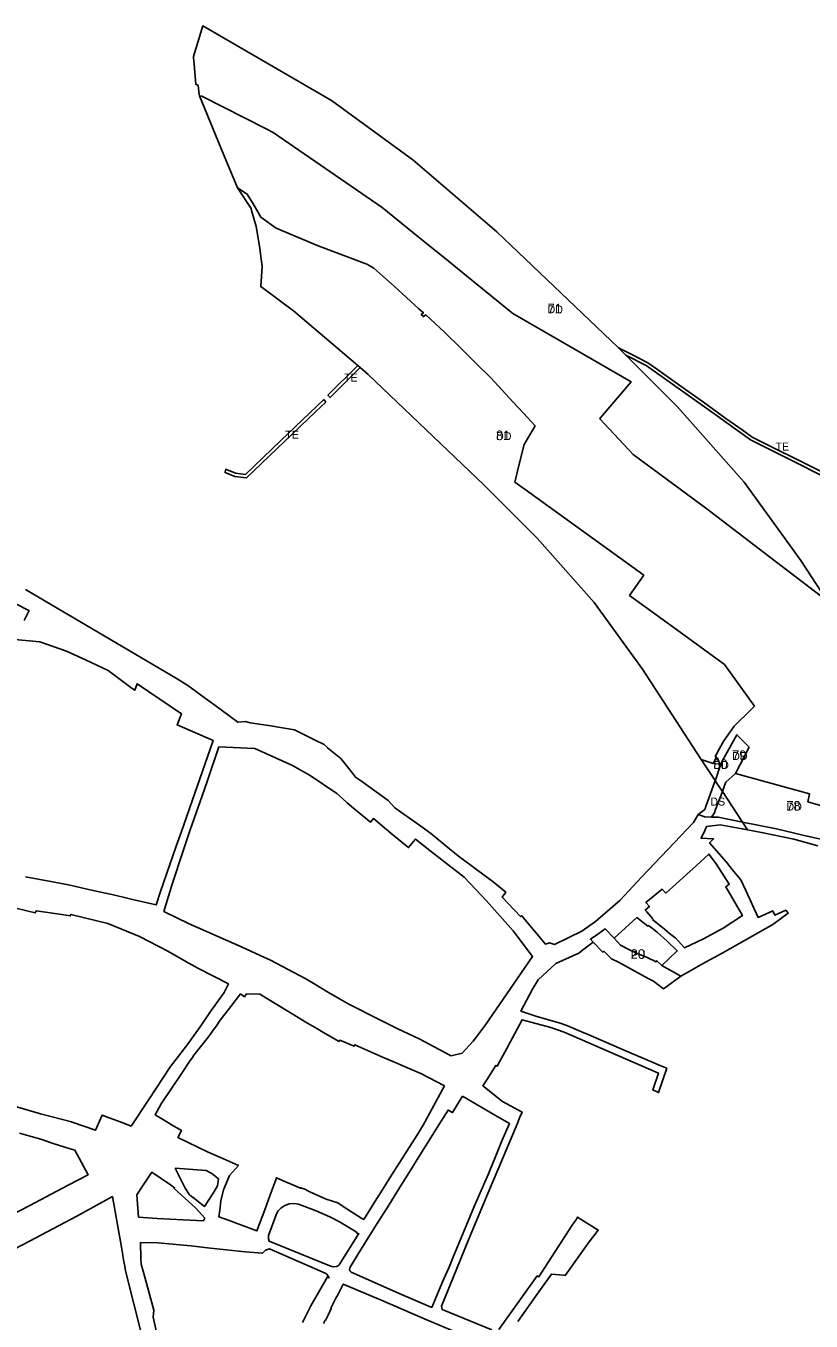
# Model space of a CAD drawing. Extents: x -545758 to -541641, y -1153152 to -1149975.
# Drawn here: x -544135 to -543644, y -1151498 to -1150689 of the extents above; entities that cross this region are included whole.
import ezdxf

# ---------------------------------------------------------------- set-up
doc = ezdxf.new("R2010")
doc.units = 0
for name, color, linetype in [('90320013', 7, 'Continuous'), ('90330013', 7, 'Continuous'), ('90330023', 7, 'Continuous'), ('90400013', 7, 'Continuous'), ('90450013', 7, 'Continuous'), ('90450023', 7, 'Continuous'), ('ID_navrh', 7, 'Continuous')]:
    doc.layers.add(name, color=color, linetype=linetype)

msp = doc.modelspace()

# ---------------------------------------------------------------- linework, layer by layer
at = {"layer": '90320013'}
msp.add_lwpolyline([(-543709.68, -1151176.38), (-543704.49, -1151161.98), (-543704.069, -1151160.82), (-543702.795, -1151162.777), (-543699.584, -1151167.645), (-543703.84, -1151178.88), (-543704.58, -1151180.83), (-543706.27, -1151183.57), (-543710.63, -1151183.4), (-543714.64, -1151182), (-543710.55, -1151178.78)], close=True, dxfattribs=at)
at = {"layer": '90330013'}
msp.add_lwpolyline([(-543622.39, -1151180.97), (-543646.12, -1151174.04), (-543645.1, -1151169.14), (-543691.46, -1151156.42), (-543682.89, -1151139.83), (-543690.45, -1151132.16), (-543699.75, -1151148.74), (-543701.13, -1151152.25), (-543700.92, -1151151.1), (-543702.64, -1151146.72), (-543703.3, -1151146.24), (-543704.04, -1151145.69), (-543703.28, -1151144.33), (-543701.31, -1151140.82), (-543698.59, -1151135.95), (-543692.28, -1151126.74), (-543681.39, -1151116.11), (-543679.42, -1151114.2), (-543698.26, -1151088.2), (-543728.18, -1151066.45), (-543757.51, -1151045.12), (-543748.74, -1151032.49), (-543822.74, -1150978.92), (-543829.21, -1150974.23), (-543826.66, -1150963.9), (-543823.42, -1150950.72), (-543816.58, -1150939.09), (-543823.76, -1150931.28), (-543830.39, -1150924.08), (-543837.13, -1150916.75), (-543844.45, -1150908.84), (-543853.71, -1150899.71), (-543862.68, -1150890.87), (-543873.19, -1150880.51), (-543884.94, -1150869.81), (-543886.25, -1150870.84), (-543887.76, -1150869.57), (-543886.4, -1150868.47), (-543889.18, -1150865.96), (-543904.7, -1150851.96), (-543911.64, -1150845.71), (-543917.39, -1150840.52), (-543921.63, -1150838.04), (-543952.16, -1150826.63), (-543978.35, -1150815.7), (-543987.95, -1150808.86), (-543990.71, -1150803.91), (-543992.64, -1150800.45), (-543996.47, -1150794.31), (-544002.61, -1150790.35), (-544005.66, -1150782.96), (-544012.92, -1150765.35), (-544026.25, -1150733.04), (-544024.7, -1150733.15), (-543984.63, -1150753.63), (-543980.18, -1150755.91), (-543912.05, -1150802.81), (-543889.76, -1150820.87), (-543886.65, -1150823.39), (-543870.95, -1150836.1), (-543865.01, -1150840.92), (-543831.46, -1150868.11), (-543830.4, -1150868.97), (-543756.47, -1150911.73), (-543776, -1150934.43), (-543776.22, -1150934.68), (-543755.27, -1150957.07), (-543709.38, -1150990.96), (-543670.14, -1151020.9), (-543608.97, -1151067.59)], dxfattribs=at)
at = {"layer": '90330023'}
for points in [[(-543831.46, -1150868.11), (-543831.46, -1150868.11), (-543865.01, -1150840.92), (-543870.95, -1150836.1), (-543886.65, -1150823.39), (-543889.76, -1150820.87), (-543912.05, -1150802.81), (-543980.18, -1150755.91), (-543984.63, -1150753.63), (-544024.7, -1150733.15), (-544026.25, -1150733.04), (-544026.37, -1150732.2), (-544027.19, -1150726.47), (-544028.18, -1150725.94), (-544028.6, -1150725.71), (-544029.66, -1150713.36), (-544030.04, -1150708.97), (-544030.08, -1150708.47), (-544024.212, -1150689.258), (-543943.707, -1150735.843), (-543892.905, -1150773.039), (-543840.462, -1150817.893), (-543764.769, -1150890.108), (-543727.838, -1150927.049), (-543685.997, -1150974.326), (-543650.498, -1151023.182), (-543634.042, -1151048.453), (-543670.14, -1151020.9), (-543709.38, -1150990.96), (-543755.27, -1150957.07), (-543776.22, -1150934.68), (-543776, -1150934.43), (-543756.47, -1150911.73), (-543830.4, -1150868.97)], [(-543779.683, -1151049.534), (-543815.282, -1151009.31), (-543848.631, -1150975.952), (-543920.938, -1150906.967), (-543925.852, -1150902.765), (-543927.383, -1150901.455), (-543967.455, -1150867.181), (-543988.016, -1150852.128), (-543987.15, -1150839.52), (-543988.46, -1150828.29), (-543990.46, -1150816.88), (-543990.87, -1150814.52), (-543993.76, -1150804.51), (-543994.07, -1150803.43), (-544002.61, -1150790.35), (-543996.47, -1150794.31), (-543992.64, -1150800.45), (-543990.71, -1150803.91), (-543987.95, -1150808.86), (-543978.35, -1150815.7), (-543952.16, -1150826.63), (-543921.63, -1150838.04), (-543917.39, -1150840.52), (-543911.64, -1150845.71), (-543904.7, -1150851.96), (-543889.18, -1150865.96), (-543886.4, -1150868.47), (-543887.76, -1150869.57), (-543886.25, -1150870.84), (-543884.94, -1150869.81), (-543873.19, -1150880.51), (-543862.68, -1150890.87), (-543853.71, -1150899.71), (-543844.45, -1150908.84), (-543837.13, -1150916.75), (-543830.39, -1150924.08), (-543823.76, -1150931.28), (-543816.58, -1150939.09), (-543823.42, -1150950.72), (-543826.66, -1150963.9), (-543829.21, -1150974.23), (-543822.74, -1150978.92), (-543748.74, -1151032.49), (-543757.51, -1151045.12), (-543728.18, -1151066.45), (-543698.26, -1151088.2), (-543679.42, -1151114.2), (-543681.39, -1151116.11), (-543692.28, -1151126.74), (-543698.59, -1151135.95), (-543701.31, -1151140.82), (-543703.28, -1151144.33), (-543704.04, -1151145.69), (-543703.3, -1151146.24), (-543705.29, -1151150.15), (-543712.747, -1151147.495), (-543749.382, -1151091.238)], [(-543703.5, -1151159.25), (-543701.13, -1151152.25), (-543699.75, -1151148.74), (-543690.45, -1151132.16), (-543682.89, -1151139.83), (-543691.46, -1151156.42), (-543697.39, -1151161.85), (-543698.15, -1151163.86), (-543699.584, -1151167.645), (-543702.795, -1151162.777), (-543704.069, -1151160.82)], [(-543704.069, -1151160.82), (-543712.747, -1151147.495), (-543705.29, -1151150.15), (-543703.3, -1151146.24), (-543702.64, -1151146.72), (-543700.92, -1151151.1), (-543701.13, -1151152.25), (-543703.5, -1151159.25)], [(-543665.68, -1151191), (-543686.982, -1151186.756), (-543699.584, -1151167.645), (-543698.15, -1151163.86), (-543697.39, -1151161.85), (-543691.46, -1151156.42), (-543645.1, -1151169.14), (-543646.12, -1151174.04), (-543622.39, -1151180.97), (-543621.56, -1151181.15), (-543619.19, -1151184.73), (-543612.4, -1151194.99), (-543608.87, -1151200.33), (-543609.43, -1151200.65), (-543619.29, -1151202.61), (-543637.18, -1151197.56), (-543649.23, -1151194.95)]]:
    msp.add_lwpolyline(points, close=True, dxfattribs=at)
msp.add_lwpolyline([(-543639.96, -1151201.49), (-543654.84, -1151197.32), (-543654.879, -1151197.312), (-543675.179, -1151193.284), (-543683.806, -1151191.571), (-543686.982, -1151186.756), (-543665.68, -1151191), (-543649.23, -1151194.95), (-543637.18, -1151197.56)], dxfattribs=at)
at = {"layer": '90400013'}
msp.add_lwpolyline([(-543610.53, -1150983.63), (-543681.92, -1150947.91), (-543696.76, -1150937.34), (-543702.88, -1150932.98), (-543702.88, -1150932.98), (-543747.19, -1150901.41), (-543759.981, -1150894.897), (-543764.552, -1150890.325), (-543756.2, -1150894.58), (-543746.15, -1150899.7), (-543740.79, -1150903.51), (-543726.08, -1150914), (-543711.46, -1150924.42), (-543697.36, -1150934.46), (-543687.16, -1150941.72), (-543680.89, -1150946.19), (-543678.05, -1150947.61), (-543665.64, -1150953.82), (-543653.68, -1150959.8), (-543637.45, -1150967.92)], dxfattribs=at)
for points in [[(-543925.852, -1150902.765), (-543944.64, -1150921.44), (-543946.01, -1150919.98), (-543927.383, -1150901.455)], [(-543947.35, -1150924.29), (-543953.47, -1150930.15), (-543977.89, -1150953.5), (-543996.79, -1150971.58), (-544004.18, -1150970.7), (-544010.23, -1150968.29), (-544010.26, -1150967.9), (-544009.85, -1150966.29), (-544009.35, -1150966.49), (-544003.69, -1150968.75), (-543997.5, -1150969.49), (-543975.44, -1150948.39), (-543948.6, -1150922.72)]]:
    msp.add_lwpolyline(points, close=True, dxfattribs=at)
at = {"layer": '90450013'}
for points in [[(-544135.83, -1151060.82), (-544132.77, -1151054.51), (-544133.31, -1151054.25), (-544155.85, -1151042.75)], [(-544135.01, -1151041.31), (-544040.31, -1151097.11), (-544037.9, -1151098.61), (-544034.19, -1151100.86), (-544032.91, -1151101.71), (-544023.35, -1151108.8), (-544016.68, -1151113.74), (-544002.35, -1151124.26), (-543997.51, -1151123.83), (-543994.53, -1151124.74), (-543981.61, -1151126.57), (-543975.61, -1151127.67), (-543966.97, -1151129.16), (-543953.58, -1151135.75), (-543948.46, -1151138.26), (-543946.15, -1151140.23), (-543946.19, -1151140.41), (-543937.89, -1151147.01), (-543931.37, -1151155.21), (-543928.69, -1151158.64), (-543925.06, -1151161.21), (-543920.47, -1151164.49), (-543908.28, -1151173.21), (-543904.16, -1151177.72), (-543888.04, -1151189.17), (-543881.98, -1151193.72), (-543868.86, -1151204.5), (-543863.57, -1151208.55), (-543856.58, -1151213.86), (-543853.29, -1151216.4), (-543842.74, -1151224.1), (-543834.93, -1151230.45), (-543837.14, -1151233.56), (-543825.8, -1151245.7), (-543825.07, -1151245.07), (-543810.15, -1151262.93), (-543807.5, -1151262.19), (-543804.52, -1151263.25), (-543787.44, -1151254.86), (-543778.92, -1151248.83), (-543763.74, -1151235.65), (-543749.81, -1151220.95), (-543717.6, -1151186.99), (-543714.64, -1151182), (-543710.63, -1151183.4), (-543706.27, -1151183.57), (-543702.17, -1151183.73), (-543686.982, -1151186.756), (-543683.806, -1151191.571), (-543687.14, -1151190.91), (-543700.87, -1151188.52), (-543709.48, -1151189.44), (-543710.44, -1151192.02), (-543712.86, -1151196.79), (-543705.09, -1151197.25), (-543707.45, -1151199.51), (-543707.61, -1151199.67), (-543696.99, -1151211.72), (-543693.35, -1151216.4), (-543690.31, -1151219.98), (-543687.97, -1151222.83), (-543684.97, -1151229.45), (-543680.64, -1151238.98), (-543677.28, -1151246.3), (-543668.09, -1151242.1), (-543666.73, -1151244.88), (-543660.02, -1151241.79), (-543658.4, -1151243.65), (-543667.96, -1151250.69), (-543683.79, -1151259.72), (-543699.65, -1151268.52), (-543712.31, -1151275.52), (-543718.88, -1151279.16), (-543725.48, -1151282.91), (-543737.45, -1151276.39), (-543727.73, -1151267.21), (-543734.01, -1151261.04), (-543740.02, -1151255.78), (-543743.2, -1151253.18), (-543745.79, -1151251.32), (-543746.06, -1151251.68), (-543752.98, -1151246.32), (-543767.08, -1151259.24), (-543772.73, -1151253.4), (-543777.43, -1151256.71), (-543782.02, -1151259.94), (-543780.39, -1151261.65), (-543786.91, -1151266.72), (-543789.27, -1151268.6), (-543803.59, -1151275.15), (-543814.61, -1151285.21), (-543818.17, -1151291.08), (-543825.45, -1151304.75), (-543816.12, -1151307.9), (-543801, -1151312.35), (-543796.67, -1151313.74), (-543785.02, -1151318.75), (-543784.788, -1151318.85), (-543763.824, -1151327.87), (-543738.03, -1151338.97), (-543734.37, -1151340.55), (-543739.44, -1151355.73), (-543743.07, -1151354.05), (-543739.57, -1151343.55), (-543764.831, -1151332.615), (-543798.52, -1151318.03), (-543806.71, -1151314.94), (-543824.69, -1151310.23), (-543832.19, -1151324.27), (-543834.23, -1151328.1), (-543838.72, -1151336.43), (-543840.3, -1151339.22), (-543841.06, -1151338.74), (-543846.72, -1151347.68), (-543849.15, -1151351.46), (-543836.99, -1151361.24), (-543824.677, -1151367.856), (-543826.23, -1151371.557), (-543827.44, -1151374.44), (-543839.67, -1151403.58), (-543846.73, -1151420.31), (-543858.23, -1151447.61), (-543875.12, -1151489.24), (-543874.59, -1151491.33), (-543843.54, -1151503.88)], [(-544135.07, -1151220.92), (-544119.1, -1151223.83), (-544108.2, -1151225.81), (-544093.63, -1151229.29), (-544079.19, -1151232.44), (-544072.2, -1151234), (-544068.15, -1151235), (-544061.61, -1151236.53), (-544053.24, -1151238.41), (-544050.68, -1151230.02), (-544040.78, -1151201.75), (-544037.55, -1151192.52), (-544017.79, -1151135.66), (-544040.27, -1151126.03), (-544037.55, -1151118.98), (-544051.12, -1151109.86), (-544065.3, -1151100.32), (-544066.7, -1151104.36), (-544068.3, -1151103.16), (-544083.41, -1151091.9), (-544097.44, -1151085.42), (-544109.42, -1151079.88), (-544125.96, -1151074.03), (-544141.57, -1151072.66)], [(-544143.24, -1151363.76), (-544125.62, -1151369.07), (-544106.19, -1151374.05), (-544105.76, -1151374.17), (-544091.17, -1151379.24), (-544087.07, -1151369.74), (-544084.39, -1151370.83), (-544073.5, -1151374.74), (-544069.05, -1151376.63), (-544057.84, -1151359.95), (-544044.72, -1151339.94), (-544044.28, -1151339.37), (-544034.31, -1151326.51), (-544025.92, -1151314.56), (-544019.28, -1151305.09), (-544010.85, -1151293.16), (-544008.14, -1151287.81), (-544027.27, -1151278.07), (-544034.7, -1151273.74), (-544046.02, -1151267.3), (-544063.84, -1151258.25), (-544083.61, -1151250.16), (-544106.61, -1151244.41), (-544107.01, -1151245.34), (-544112.23, -1151244.54), (-544128.27, -1151242.08), (-544128.88, -1151243.44), (-544147.79, -1151238.88)], [(-544144.7, -1151432.67), (-544132.32, -1151426.21), (-544118.9, -1151419.16), (-544108.27, -1151413.61), (-544096.71, -1151407.57), (-544095.8, -1151407.09), (-544104.06, -1151391.7), (-544107.12, -1151390.8), (-544117.64, -1151387.42), (-544125.4, -1151384.89), (-544131.37, -1151383.21), (-544138.76, -1151381.03)], [(-544062.12, -1151508.24), (-544072.41, -1151466.98), (-544072.89, -1151464.18), (-544073.73, -1151460.18), (-544074.39, -1151456.12), (-544075.02, -1151452.28), (-544080.63, -1151420.73), (-544102.81, -1151432.82), (-544117.9, -1151440.85), (-544132.09, -1151448.33), (-544146.42, -1151455.75)], [(-543839.26, -1151503.64), (-543833.07, -1151494.98), (-543815.25, -1151470.28), (-543814.22, -1151470.73), (-543812.44, -1151467.86), (-543793.35, -1151438.63), (-543790.79, -1151434.69), (-543790.01, -1151433.49), (-543777.13, -1151441.62), (-543782.81, -1151448.85), (-543797.73, -1151469.97), (-543798.82, -1151469.86), (-543806.39, -1151469.1), (-543812.24, -1151477.34), (-543816.4, -1151483.15), (-543827.34, -1151498.65)], [(-543961.96, -1151499.28), (-543956.79, -1151488.97), (-543946.34, -1151470.89), (-543945.23, -1151471.42), (-543946.8, -1151469.22), (-543947.72, -1151468.6), (-543982.6, -1151453.35), (-543984.94, -1151454.08), (-543986.86, -1151456.12), (-543997.75, -1151455.17), (-544009.64, -1151453.87), (-544021.2, -1151452.61), (-544031.57, -1151451.4), (-544047.8, -1151449.94), (-544052.19, -1151449.68), (-544063.02, -1151449.37), (-544062.99, -1151459.16), (-544062.69, -1151462.83), (-544061.48, -1151467.29), (-544061.07, -1151468.84), (-544054.77, -1151491.65), (-544055.23, -1151495.99), (-544051.57, -1151511.96)], [(-543865.54, -1151505.52), (-543885.28, -1151497.22), (-543913.17, -1151485.27), (-543915.75, -1151484.17), (-543936.43, -1151475.31), (-543938.15, -1151478.77), (-543940.18, -1151482.9), (-543940.36, -1151482.81), (-543942.23, -1151486.67), (-543944.1, -1151490.46), (-543943.93, -1151490.56), (-543945.93, -1151494.68), (-543947.56, -1151498.02), (-543947.76, -1151497.92), (-543948.81, -1151500.05)]]:
    msp.add_lwpolyline(points, dxfattribs=at)
for points in [[(-544043.35, -1151225.44), (-544048.52, -1151242.5), (-544032.78, -1151250.26), (-544009.98, -1151260.21), (-543999.56, -1151264.82), (-543988.26, -1151270.13), (-543981.96, -1151273), (-543959.76, -1151284.71), (-543958.85, -1151285.29), (-543954.29, -1151288.01), (-543945.7, -1151293.07), (-543938.88, -1151297.05), (-543932.89, -1151300.45), (-543914.35, -1151309.77), (-543902.35, -1151315.81), (-543888.99, -1151322.05), (-543869.81, -1151332.37), (-543869.08, -1151332.76), (-543862.17, -1151331.05), (-543855.28, -1151323.64), (-543853.15, -1151320.78), (-543847.66, -1151313.33), (-543843.07, -1151306.73), (-543832.4, -1151291.37), (-543829.61, -1151287.29), (-543818.28, -1151270.77), (-543827.85, -1151257.94), (-543830.34, -1151254.61), (-543846.98, -1151235.85), (-543853.8, -1151228.63), (-543860.89, -1151221.2), (-543876.76, -1151208.8), (-543881.27, -1151205.28), (-543891.32, -1151197.35), (-543891.6, -1151197.62), (-543895.65, -1151202.65), (-543897.46, -1151201.16), (-543906.64, -1151193.58), (-543917.59, -1151184.53), (-543919.49, -1151186.82), (-543929.88, -1151178.16), (-543933.97, -1151174.75), (-543937, -1151172.03), (-543940.51, -1151168.78), (-543957.16, -1151157.63), (-543968.25, -1151151.28), (-543991.7, -1151140.78), (-544014.15, -1151139.71), (-544021.35, -1151160.74), (-544024.64, -1151170.33), (-544032.04, -1151191.56), (-544036.38, -1151204.66)], [(-543743.22, -1151247.62), (-543735.7, -1151253.66), (-543732.87, -1151256.11), (-543729.14, -1151259.03), (-543729.01, -1151258.86), (-543723.13, -1151265.27), (-543711.35, -1151259.67), (-543699.04, -1151252.91), (-543687.02, -1151245.12), (-543697.47, -1151227.07), (-543695.27, -1151225.57), (-543703.52, -1151212.82), (-543704.8, -1151211.08), (-543707.93, -1151206.67), (-543715.75, -1151213.76), (-543722.05, -1151219.55), (-543734.92, -1151231.03), (-543737.26, -1151228.51), (-543747.36, -1151236.88), (-543745.16, -1151239.53), (-543747.71, -1151241.69), (-543746.82, -1151242.67), (-543743.07, -1151247.07)], [(-543912.31, -1151333.42), (-543929.15, -1151325.78), (-543929.62, -1151326.64), (-543938.63, -1151322.99), (-543939.02, -1151323.8), (-543939.51, -1151323.53), (-543950.3, -1151317.23), (-543952.87, -1151315.73), (-543960.21, -1151311.44), (-543967.39, -1151307.03), (-543988.58, -1151294.17), (-543996.82, -1151294.06), (-543998.16, -1151295.82), (-544000.55, -1151294.01), (-544006.68, -1151301.94), (-544013.25, -1151310.54), (-544015.73, -1151313.95), (-544017.7, -1151316.73), (-544019.62, -1151319.47), (-544021.43, -1151321.93), (-544029.71, -1151332.33), (-544030.71, -1151333.78), (-544032.11, -1151335.76), (-544037.32, -1151343.5), (-544050.12, -1151362.83), (-544053.99, -1151369.58), (-544050.83, -1151371.43), (-544044.58, -1151375.21), (-544043.68, -1151375.75), (-544038.57, -1151378.83), (-544037.56, -1151379.31), (-544039.79, -1151383.71), (-544020.87, -1151392.94), (-544013.11, -1151396.34), (-544001.97, -1151401.33), (-544007.43, -1151407.53), (-544011.35, -1151416.47), (-544012.87, -1151423.32), (-544013.54, -1151429.19), (-544014.17, -1151433.33), (-544007.69, -1151435.61), (-543990.4, -1151442.09), (-543985.44, -1151428.89), (-543982.37, -1151420.14), (-543978.64, -1151410.19), (-543978.21, -1151408.89), (-543977.18, -1151409.33), (-543974.01, -1151410.75), (-543969.97, -1151412.56), (-543969.5, -1151412.77), (-543969.01, -1151412.99), (-543963.11, -1151415.49), (-543962.95, -1151415.13), (-543960.53, -1151416.15), (-543957.73, -1151417.48), (-543954.62, -1151418.97), (-543947.03, -1151422.21), (-543943.14, -1151423.47), (-543939.91, -1151424.52), (-543936.42, -1151426.93), (-543924.89, -1151434.32), (-543923.68, -1151434.92), (-543915.42, -1151421.9), (-543914.25, -1151420.05), (-543907.95, -1151410.1), (-543907.28, -1151409.04), (-543890.49, -1151382.44), (-543886.5, -1151376.12), (-543877.15, -1151358.86), (-543873.26, -1151351.49), (-543887.96, -1151343.87), (-543891.93, -1151342.09), (-543901.19, -1151338.19), (-543903, -1151337.4)], [(-543862.03, -1151357.94), (-543868.15, -1151368.2), (-543870.94, -1151366.65), (-543876.69, -1151375.92), (-543882.51, -1151385.29), (-543888.54, -1151394.9), (-543894.27, -1151404.05), (-543901.24, -1151415.13), (-543908.02, -1151425.99), (-543915.73, -1151438.19), (-543920.92, -1151446.53), (-543927.28, -1151456.82), (-543931.59, -1151463.75), (-543932.29, -1151465.23), (-543932.44, -1151466.38), (-543932.13, -1151467.22), (-543931.47, -1151467.92), (-543928.13, -1151469.39), (-543901.43, -1151481.18), (-543881.14, -1151489.91), (-543879.06, -1151484.91), (-543874.49, -1151473.89), (-543870.36, -1151464.7), (-543867.57, -1151457.91), (-543864.92, -1151451.44), (-543859.58, -1151438.92), (-543854.57, -1151426.85), (-543850.21, -1151416.94), (-543845.74, -1151406.49), (-543844.4, -1151403.25), (-543841.56, -1151396.35), (-543837.34, -1151385.94), (-543832.58, -1151375.1), (-543841.29, -1151370.07)], [(-544028.72, -1151427.75), (-544042.06, -1151415.69), (-544041.75, -1151415.34), (-544044.34, -1151413.42), (-544056.05, -1151405.45), (-544061.89, -1151414.18), (-544065.44, -1151419.66), (-544064.32, -1151433.53), (-544052.76, -1151434.33), (-544036.42, -1151435.27), (-544023.83, -1151435.74), (-544023, -1151434.1)], [(-544032.53, -1151419.55), (-544030.4, -1151421.15), (-544030.32, -1151421.02), (-544028.02, -1151423.22), (-544023.17, -1151426.97), (-544017.3, -1151417.97), (-544014.99, -1151414.04), (-544014.31, -1151409.66), (-544018.63, -1151406.23), (-544022.15, -1151404.34), (-544041.38, -1151402.95), (-544035.18, -1151415.37)], [(-543939.06, -1151463.27), (-543926.7, -1151443.82), (-543927.51, -1151443.98), (-543928.47, -1151442.75), (-543937.67, -1151436.98), (-543937.939, -1151436.844), (-543944.83, -1151433.37), (-543953.41, -1151429.63), (-543964.36, -1151425.33), (-543967.37, -1151424.91), (-543970.28, -1151425.13), (-543973.04, -1151426.23), (-543975.52, -1151427.97), (-543977.23, -1151429.86), (-543978.45, -1151432.12), (-543983.11, -1151445.08), (-543983.05, -1151447.16), (-543982.78, -1151448.51), (-543944.8, -1151463.97), (-543942.7, -1151464.52), (-543940.7, -1151464.35), (-543939.69, -1151463.92)]]:
    msp.add_lwpolyline(points, close=True, dxfattribs=at)
at = {"layer": '90450023'}
msp.add_lwpolyline([(-543774.16, -1151268.01), (-543774.22, -1151268.06), (-543780.39, -1151261.65), (-543782.02, -1151259.94), (-543777.43, -1151256.71), (-543772.73, -1151253.4), (-543767.08, -1151259.24), (-543763.2, -1151263.64), (-543758.02, -1151266.29), (-543753.22, -1151268.54), (-543746.66, -1151271.37), (-543740.91, -1151273.96), (-543740.52, -1151273.29), (-543737.45, -1151276.39), (-543725.48, -1151282.91), (-543729.505, -1151285.851), (-543736.379, -1151290.875), (-543742.56, -1151286.1), (-543742.574, -1151286.092), (-543745.849, -1151284.322), (-543764.46, -1151274.26), (-543768.94, -1151272.07), (-543773.53, -1151267.39)], close=True, dxfattribs=at)

# ---------------------------------------------------------------- texts
at = {"layer": '90320013'}
msp.add_text('DS', height=5, rotation=0, dxfattribs=at).set_placement((-543707.112, -1151176.396))
at = {"layer": '90330023'}
for p in [(-543808.793, -1150868.856), (-543841.015, -1150948.061), (-543693.48, -1151147.915), (-543705.19, -1151153.53), (-543659.565, -1151179.515)]:
    msp.add_text('DD', height=5, rotation=360, dxfattribs=at).set_placement(p)
at = {"layer": '90400013'}
for rotation, p in [(360, (-543936.009, -1150911.447)), (0, (-543972.696, -1150947.15)), (0, (-543666.4, -1150954.558))]:
    msp.add_text('TE', height=5, rotation=rotation, dxfattribs=at).set_placement(p)
at = {"layer": '90450023'}
msp.add_text('PU', height=5, rotation=0, dxfattribs=at).set_placement((-543756.879, -1151272.138))
at = {"layer": 'ID_navrh'}
for s, rotation, p in [('71', 0, (-543808.793, -1150868.856)), ('81', 0, (-543841.015, -1150948.061)), ('79', 0, (-543693.48, -1151147.915)), ('80', 0, (-543705.19, -1151153.53)), ('78', 360, (-543659.565, -1151179.515)), ('20', 0, (-543756.879, -1151272.138))]:
    msp.add_text(s, height=6, rotation=rotation, dxfattribs=at).set_placement(p)

doc.saveas('drawing.dxf')
